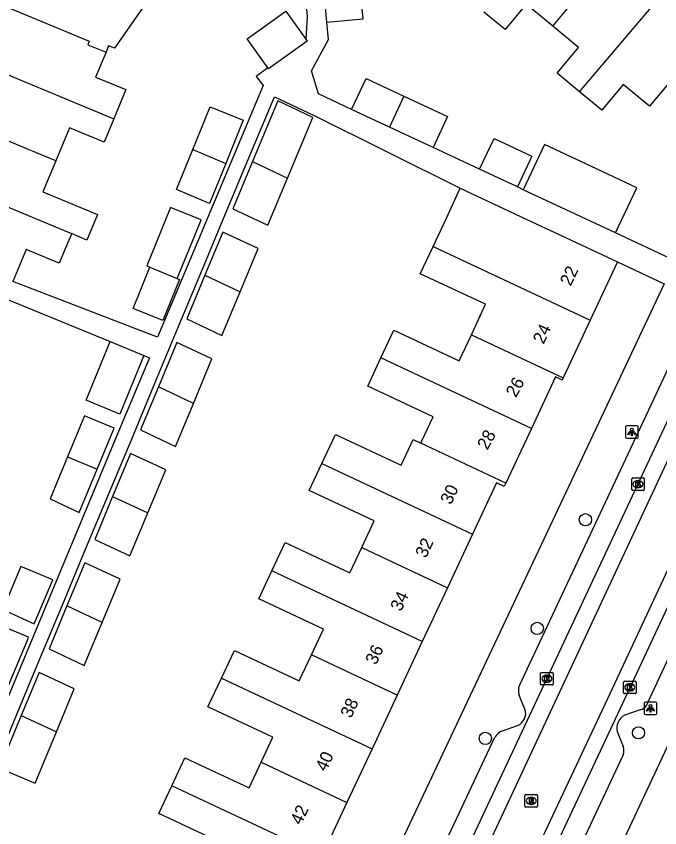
# Model space of a CAD drawing. Extents: x 159822 to 160765, y 380693 to 381634.
# Drawn here: x 160094.7 to 160145.9, y 381371.6 to 381436.2 of the extents above; entities that cross this region are included whole.
import ezdxf

# ---------------------------------------------------------------- set-up
doc = ezdxf.new("R2010")
doc.units = 0
for name, color, linetype in [('IMGEO_Boom', 7, 'Continuous'), ('IMGEO_Kolk', 7, 'Continuous'), ('IMGEO_Lichtpunt', 7, 'Continuous'), ('IMGEO_Pand', 7, 'Continuous'), ('IMGEO_Pand_nummerreeks', 7, 'Continuous'), ('IMGEO_Rijbaan_lokaal_gesloten', 7, 'Continuous'), ('IMGEO_Rioolput', 7, 'Continuous'), ('IMGEO_Voetpad_open', 7, 'Continuous')]:
    doc.layers.add(name, color=color, linetype=linetype)

msp = doc.modelspace()

# ---------------------------------------------------------------- linework, layer by layer
at = {"layer": 'IMGEO_Boom'}
for centre in [(160139.99, 381396.121), (160136.154, 381387.479), (160144.21, 381379.168), (160132.022, 381378.727)]:
    msp.add_circle(centre, 0.489, dxfattribs=at)
at = {"layer": 'IMGEO_Kolk'}
for p, q in [((160143.671, 381398.526), (160143.671, 381399.378)), ((160143.746, 381399.452), (160144.598, 381399.452)), ((160144.159, 381399.232), (160144.184, 381399.232)), ((160144.672, 381399.378), (160144.672, 381398.526)), ((160144.598, 381398.452), (160143.746, 381398.452)), ((160144.182, 381398.672), (160144.157, 381398.672)), ((160136.422, 381383.05), (160136.422, 381383.902)), ((160136.497, 381383.976), (160137.349, 381383.976)), ((160136.91, 381383.756), (160136.935, 381383.756)), ((160137.423, 381383.902), (160137.423, 381383.05)), ((160137.349, 381382.976), (160136.497, 381382.976)), ((160136.933, 381383.196), (160136.908, 381383.196)), ((160143.013, 381382.359), (160143.013, 381383.211)), ((160143.088, 381383.285), (160143.94, 381383.285)), ((160143.501, 381383.065), (160143.526, 381383.065)), ((160144.014, 381383.211), (160144.014, 381382.359)), ((160143.94, 381382.285), (160143.088, 381382.285)), ((160143.524, 381382.505), (160143.499, 381382.505))]:
    msp.add_line(p, q, dxfattribs=at)
for points in [[(160143.671, 381398.526), (160143.671, 381399.378)], [(160143.746, 381399.452), (160144.598, 381399.452)], [(160143.992, 381399.152), (160144.115, 381399.152), (160144.115, 381399.001), (160144.245, 381399.152), (160144.409, 381399.152), (160144.263, 381399.001), (160144.416, 381398.752), (160144.264, 381398.752), (160144.179, 381398.916), (160144.115, 381398.849), (160144.115, 381398.752), (160143.992, 381398.752), (160143.992, 381399.152)], [(160144.672, 381399.378), (160144.672, 381398.526)], [(160144.598, 381398.452), (160143.746, 381398.452)], [(160136.422, 381383.05), (160136.422, 381383.902)], [(160136.497, 381383.976), (160137.349, 381383.976)], [(160136.743, 381383.676), (160136.866, 381383.676), (160136.866, 381383.525), (160136.996, 381383.676), (160137.16, 381383.676), (160137.014, 381383.525), (160137.167, 381383.276), (160137.015, 381383.276), (160136.93, 381383.44), (160136.866, 381383.373), (160136.866, 381383.276), (160136.743, 381383.276), (160136.743, 381383.676)], [(160137.423, 381383.902), (160137.423, 381383.05)], [(160137.349, 381382.976), (160136.497, 381382.976)], [(160143.013, 381382.359), (160143.013, 381383.211)], [(160143.088, 381383.285), (160143.94, 381383.285)], [(160143.334, 381382.985), (160143.457, 381382.985), (160143.457, 381382.834), (160143.587, 381382.985), (160143.751, 381382.985), (160143.605, 381382.834), (160143.758, 381382.585), (160143.606, 381382.585), (160143.521, 381382.749), (160143.457, 381382.682), (160143.457, 381382.585), (160143.334, 381382.585), (160143.334, 381382.985)], [(160144.014, 381383.211), (160144.014, 381382.359)], [(160143.94, 381382.285), (160143.088, 381382.285)]]:
    msp.add_lwpolyline(points, dxfattribs=at)
for centre, start, end in [((160143.748, 381399.376), 91.55205, 178.44795), ((160143.748, 381399.376), 91.55205, 178.44795), ((160144.596, 381399.376), 1.55205, 88.44795), ((160144.596, 381399.376), 1.55205, 88.44795), ((160143.748, 381398.528), 181.55205, 268.44795), ((160143.748, 381398.528), 181.55205, 268.44795), ((160144.596, 381398.528), 271.55205, 358.44795), ((160144.596, 381398.528), 271.55205, 358.44795), ((160136.499, 381383.9), 91.55205, 178.44795), ((160136.499, 381383.9), 91.55205, 178.44795), ((160137.347, 381383.9), 1.55205, 88.44795), ((160137.347, 381383.9), 1.55205, 88.44795), ((160136.499, 381383.052), 181.55205, 268.44795), ((160136.499, 381383.052), 181.55205, 268.44795), ((160137.347, 381383.052), 271.55205, 358.44795), ((160137.347, 381383.052), 271.55205, 358.44795), ((160143.09, 381383.209), 91.55205, 178.44795), ((160143.09, 381383.209), 91.55205, 178.44795), ((160143.938, 381383.209), 1.55205, 88.44795), ((160143.938, 381383.209), 1.55205, 88.44795), ((160143.09, 381382.361), 181.55205, 268.44795), ((160143.09, 381382.361), 181.55205, 268.44795), ((160143.938, 381382.361), 271.55205, 358.44795), ((160143.938, 381382.361), 271.55205, 358.44795)]:
    msp.add_arc(centre, 0.0765, start, end, dxfattribs=at)
for centre, major_axis, ratio, start_param, end_param in [((160144.158, 381398.952), (-0.387, 0.002), 0.722429, 4.712389, 7.853982), ((160144.183, 381398.952), (-0.39, 0.002), 0.717154, 1.570796, 4.712389), ((160136.909, 381383.476), (-0.387, 0.002), 0.722429, 4.712389, 7.853982), ((160136.934, 381383.476), (-0.39, 0.002), 0.717154, 1.570796, 4.712389), ((160143.5, 381382.785), (-0.387, 0.002), 0.722429, 4.712389, 7.853982), ((160143.525, 381382.785), (-0.39, 0.002), 0.717154, 1.570796, 4.712389)]:
    msp.add_ellipse(centre, major_axis=major_axis, ratio=ratio, start_param=start_param, end_param=end_param, dxfattribs=at)
at = {"layer": 'IMGEO_Lichtpunt'}
for p, q in [((160143.176, 381403.498), (160143.176, 381402.691)), ((160143.176, 381403.498), (160143.176, 381402.691)), ((160144.078, 381403.593), (160143.27, 381403.593)), ((160144.078, 381403.593), (160143.27, 381403.593)), ((160144.172, 381402.691), (160144.172, 381403.498)), ((160144.172, 381402.691), (160144.172, 381403.498)), ((160143.27, 381402.597), (160144.078, 381402.597)), ((160143.27, 381402.597), (160144.078, 381402.597)), ((160144.661, 381381.521), (160144.661, 381380.714)), ((160144.661, 381381.521), (160144.661, 381380.714)), ((160145.563, 381381.616), (160144.755, 381381.616)), ((160145.563, 381381.616), (160144.755, 381381.616)), ((160145.657, 381380.714), (160145.657, 381381.521)), ((160145.657, 381380.714), (160145.657, 381381.521)), ((160144.755, 381380.62), (160145.563, 381380.62)), ((160144.755, 381380.62), (160145.563, 381380.62))]:
    msp.add_line(p, q, dxfattribs=at)
for points in [[(160143.55, 381403.162), (160143.589, 381403.134), (160143.401, 381402.872), (160143.363, 381402.899), (160143.55, 381403.162)], [(160143.652, 381403.114), (160143.699, 381403.114), (160143.699, 381402.792), (160143.652, 381402.792), (160143.652, 381403.114)], [(160143.762, 381403.134), (160143.8, 381403.161), (160143.987, 381402.899), (160143.948, 381402.871), (160143.762, 381403.134)], [(160145.035, 381381.185), (160145.074, 381381.157), (160144.886, 381380.895), (160144.848, 381380.922), (160145.035, 381381.185)], [(160145.137, 381381.137), (160145.184, 381381.137), (160145.184, 381380.815), (160145.137, 381380.815), (160145.137, 381381.137)], [(160145.247, 381381.157), (160145.285, 381381.184), (160145.472, 381380.922), (160145.433, 381380.894), (160145.247, 381381.157)]]:
    msp.add_lwpolyline(points, dxfattribs=at)
for centre in [(160143.675, 381403.296), (160145.16, 381381.319)]:
    msp.add_circle(centre, 0.0994, dxfattribs=at)
for centre, start, end in [((160143.27, 381403.498), 90, 180), ((160143.27, 381403.498), 90, 180), ((160144.078, 381403.498), 0, 90), ((160144.078, 381403.498), 0, 90), ((160143.27, 381402.691), 180, 270), ((160143.27, 381402.691), 180, 270), ((160144.078, 381402.691), 270, 0), ((160144.078, 381402.691), 270, 360), ((160144.755, 381381.521), 90, 180), ((160144.755, 381381.521), 90, 180), ((160145.563, 381381.521), 0, 90), ((160145.563, 381381.521), 0, 90), ((160144.755, 381380.714), 180, 270), ((160144.755, 381380.714), 180, 270), ((160145.563, 381380.714), 270, 0), ((160145.563, 381380.714), 270, 360)]:
    msp.add_arc(centre, 0.0946, start, end, dxfattribs=at)
at = {"layer": 'IMGEO_Pand'}
for points in [[(160137.393, 381435.371), (160139.112, 381437.447), (160143.989, 381443.336)], [(160107.483, 381440.764), (160102.518, 381433.625), (160102.048, 381433.82), (160101.841, 381433.323)], [(160147.927, 381440.075), (160151.796, 381436.871), (160149.436, 381434.021), (160150.464, 381433.17), (160149.636, 381431.574), (160147.912, 381430.315), (160146.877, 381431.172), (160145.087, 381429.011), (160142.991, 381430.748), (160141.294, 381428.698), (160139.52, 381430.167)], [(160139.52, 381430.167), (160147.927, 381440.075)], [(160119.414, 381435.694), (160119.245, 381437.466), (160119.076, 381439.237)], [(160119.414, 381435.694), (160122.313, 381435.97), (160121.963, 381439.486)], [(160092.495, 381437.537), (160100.506, 381434.184), (160100.384, 381433.89), (160101.841, 381433.323)], [(160137.393, 381435.371), (160135.278, 381437.123), (160133.606, 381435.103), (160131.912, 381436.505)], [(160114.705, 381432.077), (160113.066, 381434.377), (160116.153, 381436.578), (160117.745, 381434.344)], [(160139.52, 381430.167), (160137.746, 381431.636), (160139.437, 381433.679), (160137.393, 381435.371)], [(160117.745, 381434.344), (160117.852, 381434.194), (160114.765, 381431.993), (160114.705, 381432.077)], [(160101.841, 381433.323), (160101.015, 381431.335), (160103.427, 381430.332), (160102.457, 381427.998)], [(160090.582, 381432.936), (160102.457, 381427.998)], [(160121.379, 381428.765), (160122.529, 381431.223), (160125.539, 381429.814)], [(160116.277, 381423.302), (160118.288, 381428.12), (160115.5, 381429.432), (160113.488, 381424.611)], [(160125.539, 381429.814), (160124.388, 381427.357)], [(160125.539, 381429.814), (160129.015, 381428.187), (160127.865, 381425.73)], [(160108.74, 381425.578), (160110.122, 381428.97), (160112.765, 381427.893), (160112.068, 381426.181), (160111.37, 381424.469)], [(160124.388, 381427.357), (160121.379, 381428.765)], [(160097.839, 381424.659), (160095.551, 381425.61), (160088.718, 381428.451)], [(160102.457, 381427.998), (160101.687, 381426.146), (160098.933, 381427.291), (160097.839, 381424.659)], [(160127.865, 381425.73), (160124.388, 381427.357)], [(160131.569, 381423.996), (160132.719, 381426.454), (160135.731, 381425.044), (160135.722, 381425.033), (160134.578, 381422.588)], [(160111.37, 381424.469), (160110.071, 381421.282), (160107.439, 381422.384), (160108.74, 381425.578)], [(160108.74, 381425.578), (160111.37, 381424.469)], [(160142.391, 381418.932), (160144.076, 381422.532), (160140.415, 381424.245), (160136.724, 381425.973), (160135.039, 381422.372)], [(160097.839, 381424.659), (160096.821, 381422.21), (160101.17, 381420.402), (160100.324, 381418.367), (160099.098, 381418.877)], [(160113.488, 381424.611), (160111.92, 381420.856), (160114.711, 381419.547), (160116.277, 381423.302)], [(160113.488, 381424.611), (160116.277, 381423.302)], [(160086.854, 381423.967), (160099.098, 381418.877)], [(160134.578, 381422.588), (160131.569, 381423.996)], [(160127.868, 381417.861), (160128.924, 381420.116), (160130.033, 381422.485)], [(160130.033, 381422.485), (160135.264, 381420.037), (160138.003, 381418.755), (160142.531, 381416.636)], [(160142.391, 381418.932), (160138.055, 381420.961), (160135.039, 381422.372)], [(160107.511, 381415.316), (160108.907, 381418.741), (160109.407, 381419.969), (160106.972, 381420.961), (160105.083, 381416.321), (160105.34, 381416.215)], [(160112.504, 381414.259), (160113.935, 381417.689), (160111.145, 381418.998), (160109.713, 381415.568)], [(160099.098, 381418.877), (160099.058, 381418.781), (160098.81, 381418.184), (160098.2, 381416.715), (160098.118, 381416.517), (160095.484, 381417.613), (160094.422, 381415.059)], [(160130.912, 381410.828), (160132.047, 381413.254), (160126.85, 381415.687), (160127.868, 381417.861)], [(160127.868, 381417.861), (160140.36, 381411.999)], [(160142.531, 381416.636), (160140.36, 381411.999)], [(160107.511, 381415.316), (160107.694, 381415.24), (160106.359, 381411.962), (160103.999, 381412.923), (160105.34, 381416.215)], [(160105.34, 381416.215), (160107.511, 381415.316)], [(160109.713, 381415.568), (160108.263, 381412.093), (160111.053, 381410.781), (160112.504, 381414.259)], [(160109.713, 381415.568), (160112.504, 381414.259)], [(160140.36, 381411.999), (160138.209, 381407.404)], [(160123.716, 381408.999), (160124.748, 381411.204), (160129.948, 381408.769), (160130.912, 381410.828)], [(160130.912, 381410.828), (160138.209, 381407.404)], [(160104.86, 381409.18), (160102.942, 381404.521), (160100.266, 381405.64), (160102.178, 381410.284)], [(160102.178, 381410.284), (160104.86, 381409.18)], [(160108.798, 381405.376), (160110.272, 381408.91), (160107.482, 381410.222), (160106.005, 381406.683)], [(160126.896, 381402.209), (160126.982, 381402.394), (160127.879, 381404.31), (160122.664, 381406.751), (160123.716, 381408.999)], [(160135.69, 381403.384), (160123.716, 381408.999)], [(160138.209, 381407.404), (160138.128, 381407.231), (160137.606, 381407.476), (160135.69, 381403.384)], [(160106.005, 381406.683), (160104.578, 381403.263), (160107.37, 381401.955), (160108.798, 381405.376)], [(160108.798, 381405.376), (160106.005, 381406.683)], [(160101.137, 381400.138), (160102.479, 381403.398), (160100.122, 381404.383), (160098.781, 381401.125)], [(160119.024, 381400.587), (160120.105, 381402.896), (160125.333, 381400.449), (160126.29, 381402.494), (160126.896, 381402.209)], [(160135.69, 381403.384), (160133.653, 381399.032)], [(160133.653, 381399.032), (160126.896, 381402.209)], [(160098.781, 381401.125), (160097.4, 381397.77), (160099.718, 381396.692), (160101.137, 381400.138)], [(160098.781, 381401.125), (160101.137, 381400.138)], [(160105.163, 381396.665), (160106.593, 381400.091), (160103.8, 381401.399), (160102.37, 381397.973)], [(160122.184, 381393.903), (160123.177, 381396.023), (160118.018, 381398.439), (160119.024, 381400.587)], [(160119.024, 381400.587), (160131.006, 381394.979)], [(160133.653, 381399.032), (160133.533, 381398.776), (160132.918, 381399.064), (160131.006, 381394.979)], [(160102.37, 381397.973), (160100.941, 381394.548), (160103.734, 381393.241), (160105.163, 381396.665)], [(160102.37, 381397.973), (160105.163, 381396.665)], [(160131.006, 381394.979), (160129.007, 381390.709)], [(160115.03, 381392.045), (160116.091, 381394.312), (160121.246, 381391.899), (160122.184, 381393.903)], [(160122.184, 381393.903), (160129.007, 381390.709)], [(160101.528, 381387.953), (160102.958, 381391.381), (160100.164, 381392.688), (160098.734, 381389.261)], [(160093.642, 381388.987), (160096.131, 381387.829), (160097.598, 381391.342), (160095.059, 381392.396), (160093.642, 381388.987)], [(160118.183, 381385.363), (160119.147, 381387.422), (160113.995, 381389.834), (160115.03, 381392.045)], [(160127.008, 381386.439), (160115.03, 381392.045)], [(160129.007, 381390.709), (160127.008, 381386.439)], [(160098.734, 381389.261), (160097.308, 381385.843), (160100.102, 381384.536), (160101.528, 381387.953)], [(160101.528, 381387.953), (160098.734, 381389.261)], [(160093.935, 381382.569), (160095.542, 381386.419), (160095.687, 381386.765), (160092.973, 381387.898), (160091.552, 381388.492), (160089.802, 381384.3), (160091.222, 381383.705), (160091.456, 381383.607)], [(160127.008, 381386.439), (160125.008, 381382.168)], [(160111.024, 381383.507), (160112.054, 381385.708), (160117.214, 381383.292), (160118.183, 381385.363)], [(160125.008, 381382.168), (160118.183, 381385.363)], [(160097.895, 381379.244), (160099.32, 381382.661), (160096.525, 381383.969), (160095.1, 381380.553)], [(160114.183, 381376.824), (160115.113, 381378.811), (160109.956, 381381.225), (160111.024, 381383.507)], [(160111.024, 381383.507), (160123.009, 381377.898)], [(160125.008, 381382.168), (160123.009, 381377.898)], [(160095.1, 381380.553), (160093.351, 381376.362), (160096.197, 381375.175), (160097.895, 381379.244)], [(160095.1, 381380.553), (160097.895, 381379.244)], [(160123.009, 381377.898), (160121.01, 381373.628)], [(160107.073, 381374.946), (160108.121, 381377.186), (160113.232, 381374.793), (160114.183, 381376.824)], [(160114.183, 381376.824), (160121.01, 381373.628)], [(160110.226, 381368.265), (160111.192, 381370.327), (160106.04, 381372.739), (160107.073, 381374.946)], [(160119.011, 381369.358), (160107.073, 381374.946)], [(160121.01, 381373.628), (160119.011, 381369.358)]]:
    msp.add_lwpolyline(points, dxfattribs=at)
at = {"layer": 'IMGEO_Rijbaan_lokaal_gesloten'}
for points in [[(160109.962, 381325.916), (160159.942, 381432.616)], [(160161.388, 381432.416), (160149.403, 381406.998), (160131.419, 381368.47), (160113.872, 381331.126), (160111.169, 381325.358)], [(160114.453, 381323.839), (160117.12, 381329.501), (160141.773, 381381.897), (160157.697, 381416.082), (160164.648, 381430.832)], [(160165.725, 381430.065), (160154.812, 381406.917), (160141.981, 381379.468), (160115.621, 381323.299)]]:
    msp.add_lwpolyline(points, dxfattribs=at)
at = {"layer": 'IMGEO_Rioolput'}
for p, q in [((160135.174, 381373.33), (160135.174, 381374.182)), ((160135.249, 381374.256), (160136.101, 381374.256)), ((160135.662, 381374.036), (160135.687, 381374.036)), ((160136.175, 381374.182), (160136.175, 381373.33)), ((160136.101, 381373.256), (160135.249, 381373.256)), ((160135.685, 381373.476), (160135.66, 381373.476))]:
    msp.add_line(p, q, dxfattribs=at)
for points in [[(160135.174, 381373.33), (160135.174, 381374.182)], [(160135.249, 381374.256), (160136.101, 381374.256)], [(160135.763, 381373.954), (160135.511, 381373.956), (160135.511, 381373.556)], [(160135.511, 381373.556), (160135.635, 381373.556), (160135.635, 381373.718), (160135.646, 381373.718)], [(160135.689, 381373.875), (160135.635, 381373.875), (160135.635, 381373.794)], [(160135.635, 381373.794), (160135.687, 381373.794)], [(160136.175, 381374.182), (160136.175, 381373.33)], [(160136.101, 381373.256), (160135.249, 381373.256)], [(160135.693, 381373.689), (160135.764, 381373.556), (160135.904, 381373.556), (160135.839, 381373.682)]]:
    msp.add_lwpolyline(points, dxfattribs=at)
for centre, radius, start, end in [((160135.251, 381374.18), 0.0765, 91.55205, 178.44795), ((160135.251, 381374.18), 0.0765, 91.55205, 178.44795), ((160135.645, 381373.665), 0.0533, 26.02933, 88.69889), ((160135.671, 381373.983), 0.19, 274.7715, 282.96867), ((160135.695, 381373.779), 0.0964, 77.00612, 93.18647), ((160135.709, 381373.836), 0.0378, 276.66336, 79.67722), ((160135.762, 381373.844), 0.109, 350.36119, 89.41601), ((160135.76, 381373.844), 0.112, 277.58423, 350.98172), ((160135.744, 381373.629), 0.108, 29.51342, 73.79051), ((160136.099, 381374.18), 0.0765, 1.55205, 88.44795), ((160136.099, 381374.18), 0.0765, 1.55205, 88.44795), ((160135.251, 381373.332), 0.0765, 181.55205, 268.44795), ((160135.251, 381373.332), 0.0765, 181.55205, 268.44795), ((160136.099, 381373.332), 0.0765, 271.55205, 358.44795), ((160136.099, 381373.332), 0.0765, 271.55205, 358.44795)]:
    msp.add_arc(centre, radius, start, end, dxfattribs=at)
for centre, major_axis, ratio, start_param, end_param in [((160135.661, 381373.756), (-0.387, 0.002), 0.722429, 4.712389, 7.853982), ((160135.686, 381373.756), (-0.39, 0.002), 0.717154, 1.570796, 4.712389)]:
    msp.add_ellipse(centre, major_axis=major_axis, ratio=ratio, start_param=start_param, end_param=end_param, dxfattribs=at)
at = {"layer": 'IMGEO_Voetpad_open'}
for points in [[(160118.734, 381442.832), (160118.598, 381444.261), (160117.155, 381444.135), (160117.85, 381436.15), (160117.745, 381434.344)], [(160121.379, 381428.765), (160118.748, 381429.996), (160118.188, 381431.819), (160119.545, 381434.316), (160119.414, 381435.694)], [(160114.705, 381432.077), (160113.796, 381431.38), (160114.336, 381430.674), (160105.95, 381410.653), (160094.422, 381415.059)], [(160134.728, 381382.935), (160157.309, 381431.021)], [(160092.331, 381375.188), (160092.693, 381376.128), (160093.015, 381376.502), (160094.77, 381380.707), (160096.588, 381385.063), (160098.404, 381389.416), (160100.222, 381393.773), (160102.039, 381398.128), (160103.857, 381402.485), (160105.673, 381406.838), (160107.54, 381411.312), (160109.38, 381415.724), (160111.198, 381420.081), (160113.154, 381424.768), (160113.495, 381425.585), (160115.237, 381429.759), (160118.359, 381428.29), (160130.033, 381422.485)], [(160131.569, 381423.996), (160127.865, 381425.73)], [(160135.039, 381422.372), (160134.578, 381422.588)], [(160147.119, 381416.719), (160142.391, 381418.932)], [(160142.531, 381416.636), (160146.257, 381414.891)], [(160090.993, 381414.866), (160102.178, 381410.284)], [(160146.257, 381414.891), (160105.356, 381328.134)], [(160104.86, 381409.18), (160105.289, 381409.003), (160102.837, 381403.126), (160096.781, 381388.612), (160092.333, 381377.953), (160092.229, 381377.996)], [(160155.081, 381405.884), (160155.459, 381404.675), (160155.464, 381404.329), (160155.38, 381403.902), (160144.913, 381381.545), (160144.86, 381381.385)], [(160118.127, 381317.544), (160158.582, 381403.815)], [(160135.176, 381381.054), (160134.711, 381382.172)], [(160144.331, 381381.01), (160143.112, 381380.563)], [(160133.387, 381379.323), (160134.574, 381379.747)], [(160142.522, 381379.261), (160143.002, 381378.083)], [(160110.034, 381327.483), (160109.616, 381328.709), (160109.585, 381329.153), (160109.637, 381329.493), (160132.786, 381378.835)], [(160142.987, 381377.43), (160118.484, 381325.176)]]:
    msp.add_lwpolyline(points, dxfattribs=at)
for centre, radius, start, end in [((160135.748, 381382.531), 1.097, 158.36532, 199.08195), ((160134.191, 381380.716), 1.042, 291.58599, 18.95272), ((160144.209, 381381.743), 0.743, 279.4456, 331.21889), ((160143.588, 381379.563), 1.108, 115.44965, 195.79513), ((160133.827, 381378.168), 1.236, 110.82957, 147.32225), ((160142.096, 381377.777), 0.956, 338.70678, 18.66142)]:
    msp.add_arc(centre, radius, start, end, dxfattribs=at)

# ---------------------------------------------------------------- texts
at = {"layer": 'IMGEO_Pand_nummerreeks'}
for s, rotation, p in [('22', 64.91311, (160138.816, 381414.646)), ('24', 64.91311, (160136.657, 381410.033)), ('26', 61.44433, (160134.462, 381405.789)), ('28', 61.44399, (160132.186, 381401.607)), ('30', 64.91612, (160129.293, 381397.263)), ('32', 64.91382, (160127.301, 381393.011)), ('34', 64.91382, (160125.315, 381388.767)), ('36', 64.91382, (160123.327, 381384.52)), ('38', 64.91382, (160121.339, 381380.275)), ('40', 64.91382, (160119.351, 381376.028)), ('42', 64.91382, (160117.36, 381371.775))]:
    msp.add_text(s, height=1, rotation=rotation, dxfattribs=at).set_placement(p)

doc.saveas('drawing.dxf')
